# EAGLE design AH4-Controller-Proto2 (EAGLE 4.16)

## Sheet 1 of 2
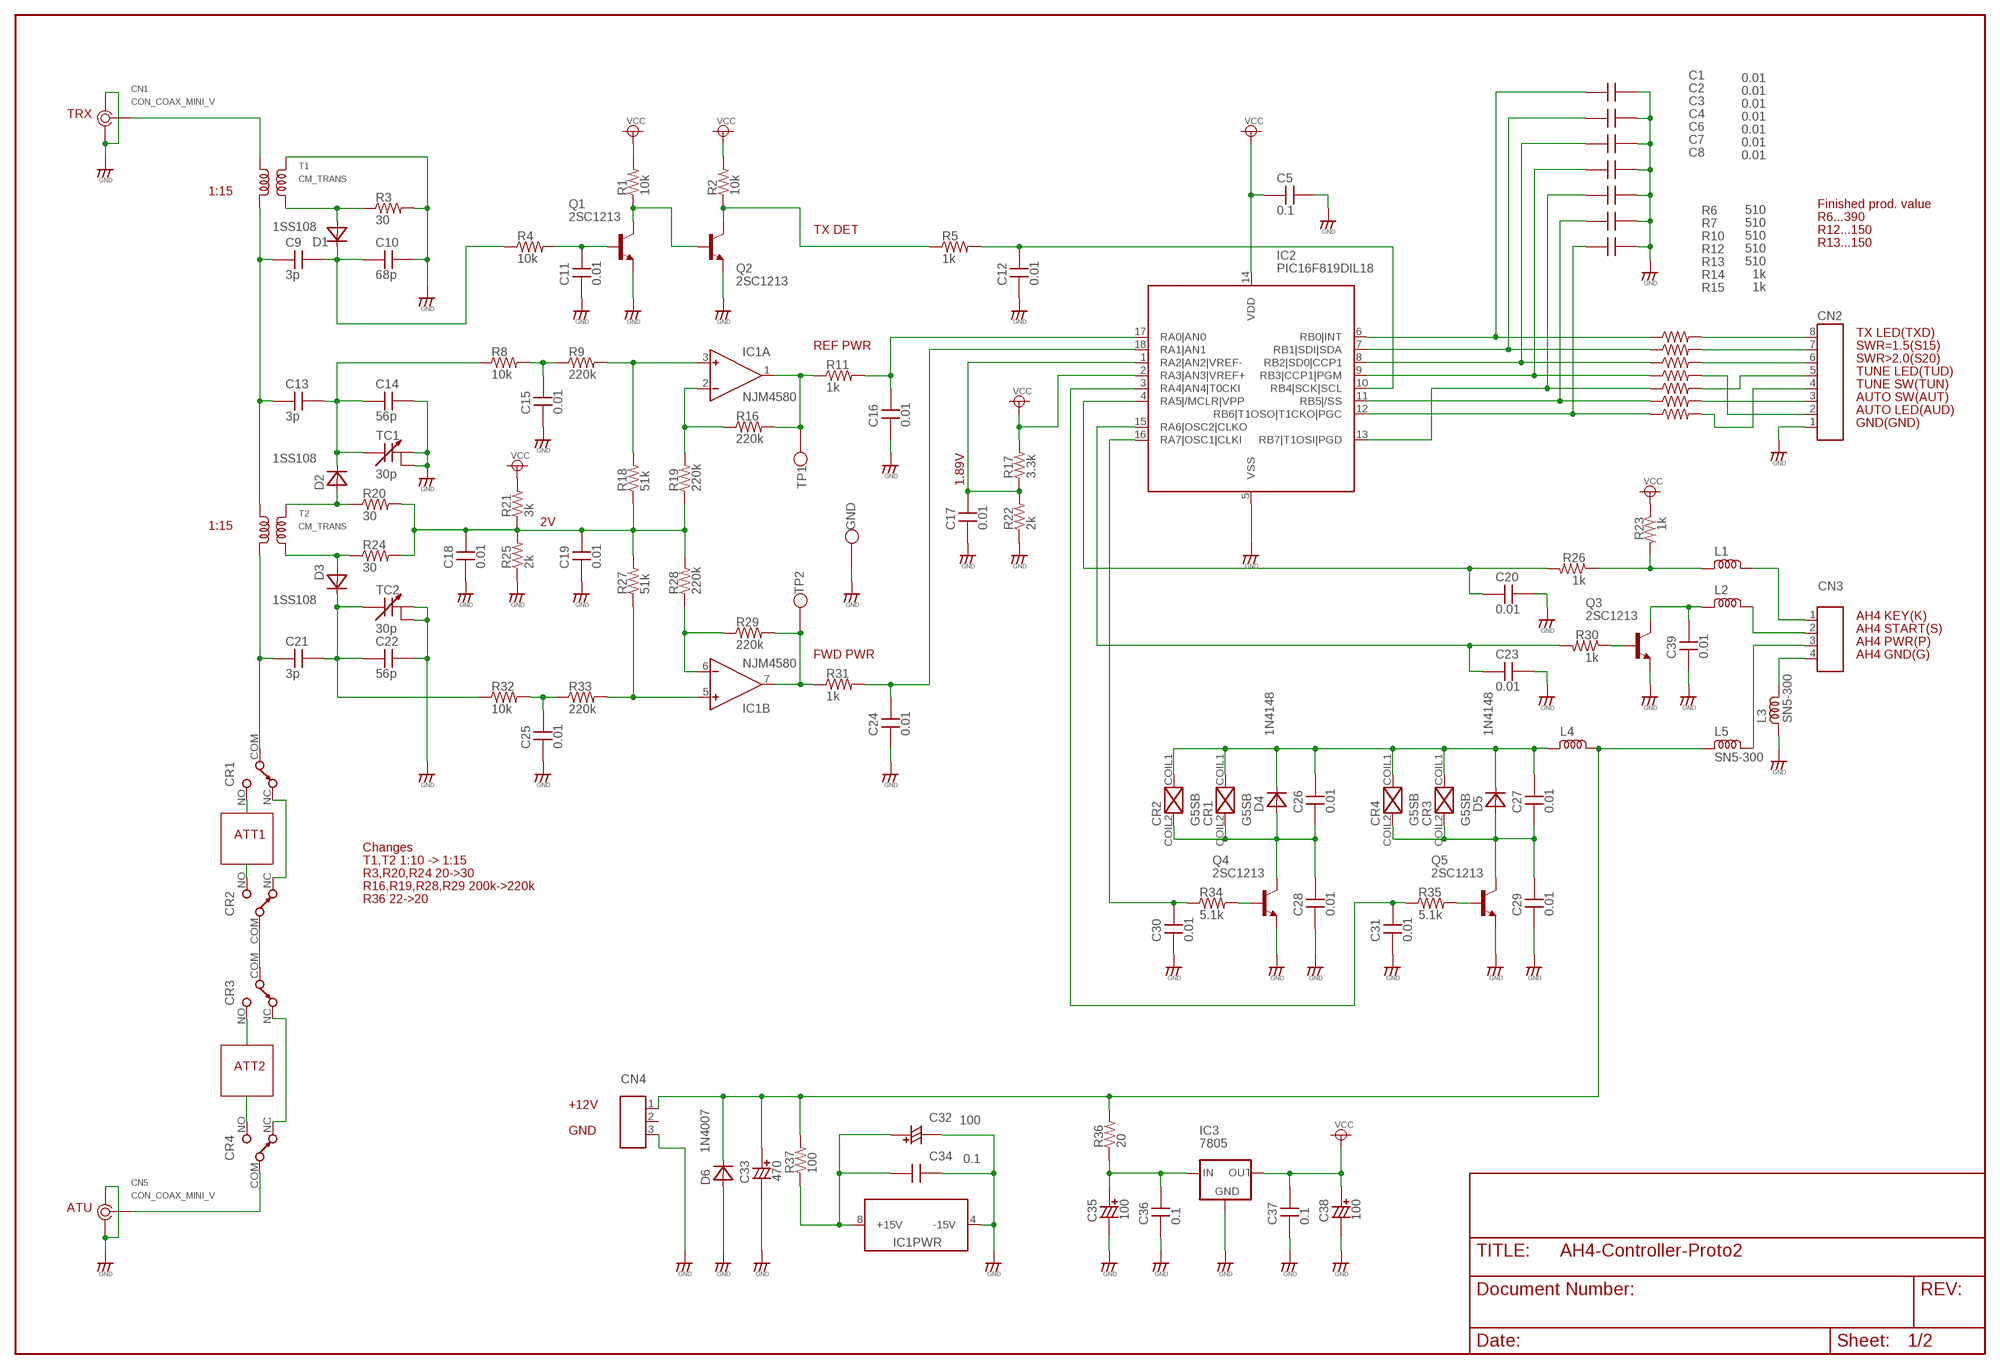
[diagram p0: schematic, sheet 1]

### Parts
C1  0.01  CAPDIP_2  [CAP_DIP_2]
C2  0.01  CAPDIP_2  [CAP_DIP_2]
C3  0.01  CAPDIP_2  [CAP_DIP_2]
C4  0.01  CAPDIP_2  [CAP_DIP_2]
C5  0.1  CAPDIP_2  [CAP_DIP_2]
C6  0.01  CAPDIP_2  [CAP_DIP_2]
C7  0.01  CAPDIP_2  [CAP_DIP_2]
C8  0.01  CAPDIP_2  [CAP_DIP_2]
C9  3p  CAPDIP_2  [CAP_DIP_2]
C10  68p  CAPDIP_2  [CAP_DIP_2]
C11  0.01  CAPDIP_2  [CAP_DIP_2]
C12  0.01  CAPDIP_2  [CAP_DIP_2]
C13  3p  CAPDIP_2  [CAP_DIP_2]
C14  56p  CAPDIP_2  [CAP_DIP_2]
C15  0.01  CAPDIP_2  [CAP_DIP_2]
C16  0.01  CAPDIP_2  [CAP_DIP_2]
C17  0.01  CAPDIP_2  [CAP_DIP_2]
C18  0.01  CAPDIP_2  [CAP_DIP_2]
C19  0.01  CAPDIP_2  [CAP_DIP_2]
C20  0.01  CAPDIP_2  [CAP_DIP_2]
C21  3p  CAPDIP_2  [CAP_DIP_2]
C22  56p  CAPDIP_2  [CAP_DIP_2]
C23  0.01  CAPDIP_2  [CAP_DIP_2]
C24  0.01  CAPDIP_2  [CAP_DIP_2]
C25  0.01  CAPDIP_2  [CAP_DIP_2]
C26  0.01  CAPDIP_2  [CAP_DIP_2]
C27  0.01  CAPDIP_2  [CAP_DIP_2]
C28  0.01  CAPDIP_2  [CAP_DIP_2]
C29  0.01  CAPDIP_2  [CAP_DIP_2]
C30  0.01  CAPDIP_2  [CAP_DIP_2]
C31  0.01  CAPDIP_2  [CAP_DIP_2]
C32  100  CCAP6.5  [CCAP_6.5]
C33  470  CCAP8.5  [CCAP_8.5]
C34  0.1  CAPDIP_2  [CAP_DIP_2]
C35  100  CCAP6.5  [CCAP_6.5]
C36  0.1  CAPDIP_2  [CAP_DIP_2]
C37  0.1  CAPDIP_2  [CAP_DIP_2]
C38  100  CCAP6.5  [CCAP_6.5]
C39  0.01  CAPDIP_2  [CAP_DIP_2]
CN1  CON_COAX_MINI_V  [CON_COAX_MINI_V]
CN2  CON_8P  [CON_HRS_DIP_8]
CN3  CON_4P  [CON_HRS_DIP_4]
CN4  CON_3P  [CON_HRS_DIP_3]
CN5  CON_COAX_MINI_V  [CON_COAX_MINI_V]
CR1  G5SB  [G5SB]
CR2  G5SB  [G5SB]
CR3  G5SB  [G5SB]
CR4  G5SB  [G5SB]
D1  1SS108  DIODEGENERIC_2  [DIODE_2]
D2  1SS108  DIODEGENERIC_2  [DIODE_2]
D3  1SS108  DIODEGENERIC_2  [DIODE_2]
D4  1N4148  DIODEGENERIC_2  [DIODE_2]
D5  1N4148  DIODEGENERIC_2  [DIODE_2]
D6  1N4007  DIODEGENERIC_3  [DIODE_3]
GND  TP  [TP]
IC1  NJM4580  [DIL08]
IC2  PIC16F819DIL18  [DIL18]
IC3  7805  78XXVIRT  [TO220-VIRT]
L1  L  [MICRO_INDUCTOR]
L2  L  [MICRO_INDUCTOR]
L3  SN5-300  LSN5-300  [SN5-300]
L4  L  [MICRO_INDUCTOR]
L5  SN5-300  LSN5-300  [SN5-300]
Q1  2SC1213  2SC1815  [TO92]
Q2  2SC1213  2SC1815  [TO92]
Q3  2SC1213  2SC1815  [TO92]
Q4  2SC1213  2SC2236  [TO92]
Q5  2SC1213  2SC2236  [TO92]
R1  10k  R0.125W_2P  [R_0.125W_2]
R2  10k  R0.125W_2P  [R_0.125W_2]
R3  30  R0.125W_2P  [R_0.125W_2]
R4  10k  R0.125W_2P  [R_0.125W_2]
R5  1k  R0.125W_2P  [R_0.125W_2]
R6  510  R0.125W_2P  [R_0.125W_2]
R7  510  R0.125W_2P  [R_0.125W_2]
R8  10k  R0.125W_2P  [R_0.125W_2]
R9  220k  R0.125W_2P  [R_0.125W_2]
R10  510  R0.125W_2P  [R_0.125W_2]
R11  1k  R0.125W_2P  [R_0.125W_2]
R12  510  R0.125W_2P  [R_0.125W_2]
R13  510  R0.125W_2P  [R_0.125W_2]
R14  1k  R0.125W_2P  [R_0.125W_2]
R15  1k  R0.125W_2P  [R_0.125W_2]
R16  220k  R0.125W_2P  [R_0.125W_2]
R17  3.3k  R0.125W_2P  [R_0.125W_2]
R18  51k  R0.125W_2P  [R_0.125W_2]
R19  220k  R0.125W_2P  [R_0.125W_2]
R20  30  R0.125W_2P  [R_0.125W_2]
R21  3k  R0.125W_2P  [R_0.125W_2]
R22  2k  R0.125W_2P  [R_0.125W_2]
R23  1k  R0.125W_2P  [R_0.125W_2]
R24  30  R0.125W_2P  [R_0.125W_2]
R25  2k  R0.125W_2P  [R_0.125W_2]
R26  1k  R0.125W_2P  [R_0.125W_2]
R27  51k  R0.125W_2P  [R_0.125W_2]
R28  220k  R0.125W_2P  [R_0.125W_2]
R29  220k  R0.125W_2P  [R_0.125W_2]
R30  1k  R0.125W_2P  [R_0.125W_2]
R31  1k  R0.125W_2P  [R_0.125W_2]
R32  10k  R0.125W_2P  [R_0.125W_2]
R33  220k  R0.125W_2P  [R_0.125W_2]
R34  5.1k  R0.125W_2P  [R_0.125W_2]
R35  5.1k  R0.125W_2P  [R_0.125W_2]
R36  20  R0.125W_2P  [R_0.125W_2]
R37  100  R0.125W_3P  [R_0.125W_3]
T1  CM_TRANS  [CM_TRANS]
T2  CM_TRANS  [CM_TRANS]
TC1  30p  TCAP  [TC_PHILLIPS]
TC2  30p  TCAP  [TC_PHILLIPS]
TP1  TP  [TP]
TP2  TP  [TP]

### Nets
12V: C33.+ CN4.1 D6.K L4.2 L5.1 R36.2 R37.2
ATT1_IN: CR1.NO ; also sheet 2
ATT1_OUT: CR2.NO ; also sheet 2
ATT2_IN: CR3.NO ; also sheet 2
ATT2_OUT: CR4.NO ; also sheet 2
CN1: CN1.HOT T1.P1
CN3: CN5.HOT CR4.COM
DVCC: C5.1 C37.2 C38.+ IC2.2(RA3|AN3|VREF+) IC2.14(VDD) IC3.3(OUT) R1.2 R2.2 R17.2 R21.2 R23.1 ; supply symbol labelled VCC
GND: C1.2 C2.2 C3.2 C4.2 C5.2 C6.2 C7.2 C8.2 C10.2 C11.1 C12.1 C14.2 C15.1 C16.1 C17.1 C18.1 C19.1 C20.2 C22.2 C23.2 C24.1 C25.1 C28.1 C29.1 C30.1 C31.1 C32.- C33.- C34.2 C35.- C36.1 C37.1 C38.- C39.1 CN1.COLD1 CN1.COLD2 CN2.1 CN4.3 CN5.COLD1 CN5.COLD2 D6.A GND.TP IC1.4(PWR:-15V) IC2.5(VSS) IC3.2(GND) L3.1 Q1.1(E) Q2.1(E) Q3.1(E) Q4.1(E) Q5.1(E) R3.2 R22.1 R25.1 T1.S1 TC1.ROT-1 TC1.ROT-2 TC2.ROT-1 TC2.ROT-2 ; also sheet 2
N$1: C15.2 R8.2 R9.1
N$2: IC1.3(A:IN+) R9.2 R18.2
N$3: IC1.2(A:IN-) R16.1 R19.2
N$4: C31.2 IC2.3(RA4|AN4|T0CKI) R35.1
N$5: C25.2 R32.2 R33.1
N$6: IC1.5(B:IN+) R27.1 R33.2
N$7: IC1.1(A:OUT) R11.1 R16.2 TP1.TP
N$8: C24.2 IC2.18(RA1|AN1) R31.2
N$9: C13.2 C14.1 D2.K R8.1 TC1.ST
N$10: C21.2 C22.1 D3.K R32.1 TC2.ST
N$11: C16.2 IC2.17(RA0|AN0) R11.2
N$12: L1.1 R23.2 R26.1
N$13: Q1.2(C) Q2.3(B) R1.1
N$14: C26.1 C28.2 CR1.COIL2 CR2.COIL2 D4.A Q4.2(C)
N$15: CN3.1 L1.2
N$16: C12.2 IC2.10(RB4|SCK|SCL) R5.2
N$17: C9.1 C13.1 T1.P2 T2.P1
N$18: C1.1 IC2.6(RB0|INT) R6.1
N$19: C2.1 IC2.7(RB1|SDI|SDA) R7.1
N$20: C7.1 IC2.11(RB5|/SS) R14.1
N$21: C4.1 IC2.9(RB3|CCP1|PGM) R12.1
N$22: CN3.2 L2.2
N$23: C8.1 IC2.12(RB6|T1OSO|T1CKO|PGC) R15.1
N$24: CN2.8 R6.2
N$25: CN2.7 R7.2
N$26: CN2.6 R10.2
N$27: CN2.2 R12.2
N$28: C6.1 IC2.13(RB7|T1OSI|PGD) R13.1
N$29: D1.A R3.1 T1.S2
N$30: IC1.6(B:IN-) R28.1 R29.1
N$31: IC1.7(B:OUT) R29.2 R31.1 TP2.TP
N$32: D3.A R24.1 T2.S2
N$33: CN3.3 L5.2
N$34: C18.2 C19.2 R18.1 R19.1 R20.2 R21.1 R24.2 R25.2 R27.2 R28.2
N$35: CN2.5 R13.2
N$36: Q3.3(B) R30.1
N$37: CN2.3 R14.2
N$38: C20.1 IC2.4(RA5|/MCLR|VPP) R26.2
N$39: C30.2 IC2.16(RA7|OSC1|CLKI) R34.1
N$41: C35.+ C36.2 IC3.1(IN) R36.1
N$42: C32.+ C34.1 IC1.8(PWR:+15V) R37.1
N$43: C23.1 IC2.15(RA6|OSC2|CLKO) R30.2
N$44: CN2.4 R15.2
N$45: C9.2 C10.1 D1.K R4.1
N$46: CN3.4 L3.2
N$47: C11.2 Q1.3(B) R4.2
N$48: C17.2 IC2.1(RA2|AN2|VREF-) R17.1 R22.2
N$49: Q2.2(C) R2.1 R5.1
N$50: CR1.NC CR2.NC
N$51: C39.2 L2.1 Q3.2(C)
N$52: C3.1 IC2.8(RB2|SD0|CCP1) R10.1
N$53: CR3.NC CR4.NC
N$54: C27.1 C29.2 CR3.COIL2 CR4.COIL2 D5.A Q5.2(C)
N$55: C21.1 CR1.COM T2.P2
N$56: CR2.COM CR3.COM
N$57: C26.2 C27.2 CR1.COIL1 CR2.COIL1 CR3.COIL1 CR4.COIL1 D4.K D5.K L4.1
N$58: Q5.3(B) R35.2
N$59: Q4.3(B) R34.2
T1: D2.A R20.1 T2.S1
Unconnected: CN4.2

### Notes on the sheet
- TRX
- 1:15
- Finished prod. value
- R6...390
- TX DET | R12...150
- R13...150
- TX LED(TXD)
- REF PWR | SWR=1.5(S15)
- SWR>2.0(S20)
- TUNE LED(TUD)
- TUNE SW(TUN)
- AUTO SW(AUT)
- AUTO LED(AUD)
- GND(GND)
- 1.89V
- 2V
- 1:15
- AH4 KEY(K)
- AH4 START(S)
- AH4 PWR(P)
- FWD PWR | AH4 GND(G)
- ATT1
- Changes
- T1,T2 1:10 -> 1:15
- R3,R20,R24 20->30
- R16,R19,R28,R29 200k->220k
- R36 22->20
- ATT2
- +12V
- GND
- ATU

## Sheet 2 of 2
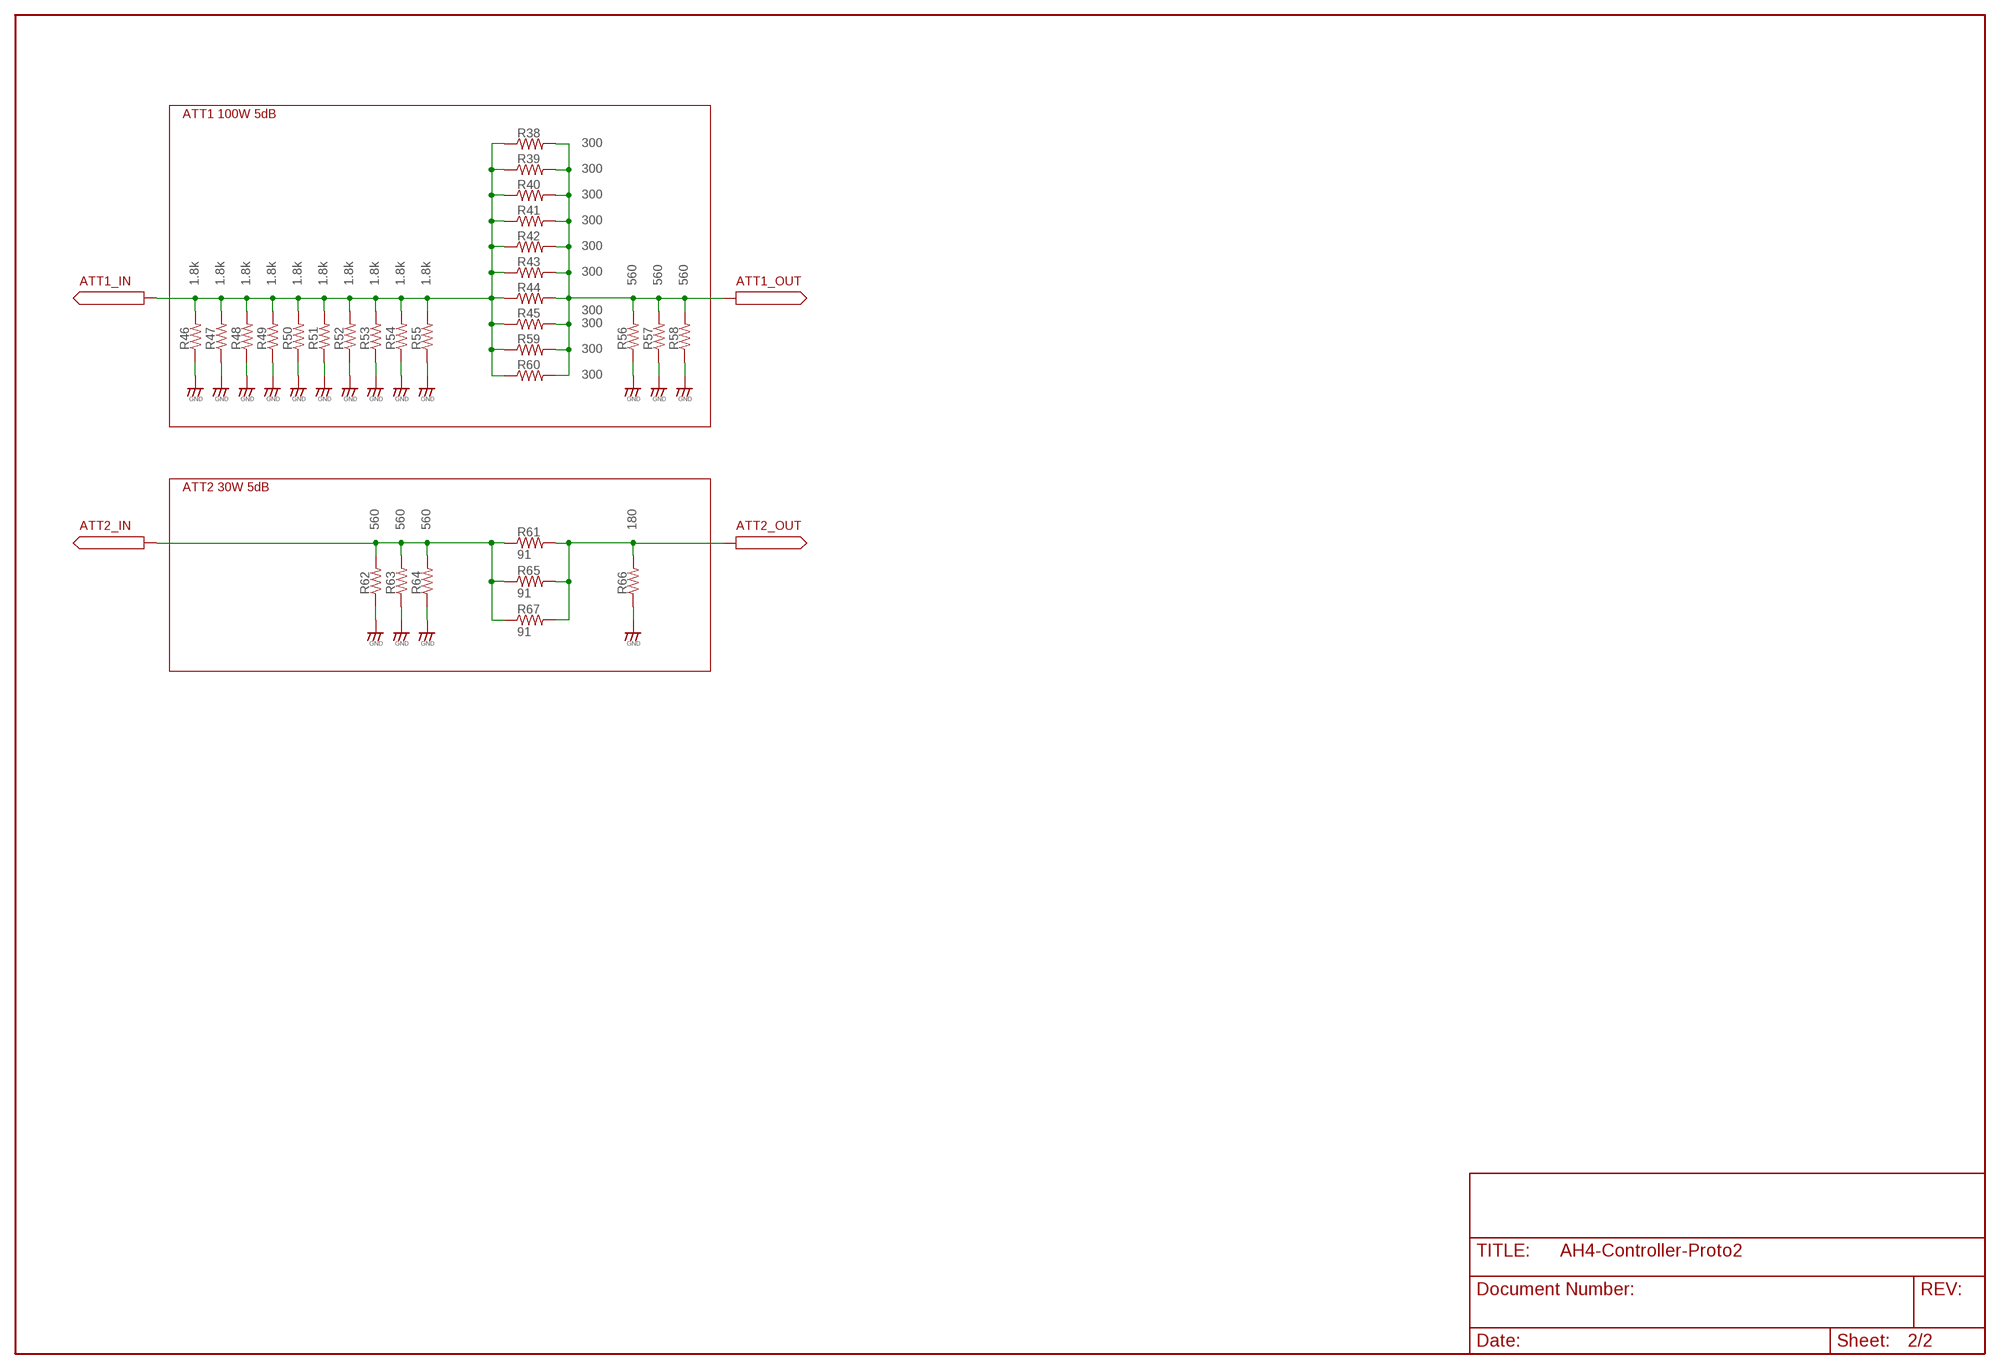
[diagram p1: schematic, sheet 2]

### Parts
R38  300  R3W_7  [R_3W_7]
R39  300  R3W_7  [R_3W_7]
R40  300  R3W_7  [R_3W_7]
R41  300  R3W_7  [R_3W_7]
R42  300  R3W_7  [R_3W_7]
R43  300  R3W_7_STACK  [R_3W_7_STACK]
R44  300  R3W_7_STACK  [R_3W_7_STACK]
R45  300  R3W_7_STACK  [R_3W_7_STACK]
R46  1.8k  R3W_7  [R_3W_7]
R47  1.8k  R3W_7  [R_3W_7]
R48  1.8k  R3W_7  [R_3W_7]
R49  1.8k  R3W_7  [R_3W_7]
R50  1.8k  R3W_7  [R_3W_7]
R51  1.8k  R3W_7_STACK  [R_3W_7_STACK]
R52  1.8k  R3W_7_STACK  [R_3W_7_STACK]
R53  1.8k  R3W_7_STACK  [R_3W_7_STACK]
R54  1.8k  R3W_7_STACK  [R_3W_7_STACK]
R55  1.8k  R3W_7_STACK  [R_3W_7_STACK]
R56  560  R3W_7  [R_3W_7]
R57  560  R3W_7  [R_3W_7]
R58  560  R3W_7_STACK  [R_3W_7_STACK]
R59  300  R3W_7_STACK  [R_3W_7_STACK]
R60  300  R3W_7_STACK  [R_3W_7_STACK]
R61  91  R3W_7  [R_3W_7]
R62  560  R3W_7_STACK  [R_3W_7_STACK]
R63  560  R3W_7  [R_3W_7]
R64  560  R3W_7  [R_3W_7]
R65  91  R3W_7_STACK  [R_3W_7_STACK]
R66  180  R3W_7  [R_3W_7]
R67  91  R3W_7  [R_3W_7]

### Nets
ATT1_IN: R38.1 R39.1 R40.1 R41.1 R42.1 R43.1 R44.1 R45.1 R46.2 R47.2 R48.2 R49.2 R50.2 R51.2 R52.2 R53.2 R54.2 R55.2 R59.1 R60.1 ; also sheet 1
ATT1_OUT: R38.2 R39.2 R40.2 R41.2 R42.2 R43.2 R44.2 R45.2 R56.2 R57.2 R58.2 R59.2 R60.2 ; also sheet 1
ATT2_IN: R61.1 R62.2 R63.2 R64.2 R65.1 R67.1 ; also sheet 1
ATT2_OUT: R61.2 R65.2 R66.2 R67.2 ; also sheet 1
GND: R46.1 R47.1 R48.1 R49.1 R50.1 R51.1 R52.1 R53.1 R54.1 R55.1 R56.1 R57.1 R58.1 R62.1 R63.1 R64.1 R66.1 ; also sheet 1

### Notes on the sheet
- ATT1 100W 5dB
- ATT1_IN | ATT1_OUT
- ATT2 30W 5dB
- ATT2_IN | ATT2_OUT

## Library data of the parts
C1-C31 C34 C36 C37 C39 = AH4-Controller:CAP: Non polar capacitor
C32 C33 C35 C38 = AH4-Controller:CCAP: Polar capacitor
CN1 CN5 = AH4-Controller:CON_COAX_MINI_V
CN2 = AH4-Controller:CON_8P
CN3 = AH4-Controller:CON_4P
CN4 = AH4-Controller:CON_3P
CR1-CR4 = AH4-Controller:G5SB
D1-D6 = AH4-Controller:DIODE
GND TP1 TP2 = AH4-Controller:TP
IC1 = AH4-Controller:NJM4580: Audio opamp
IC2 = AH4-Controller:PIC16F819: PIC MICRO (16 I/O 10bit-5ch ADC 20MHz)
IC3 = AH4-Controller:78XX
L1-L5 = AH4-Controller:L
Q1-Q3 = AH4-Controller:2SC1815: General use NPN transistor
Q4 Q5 = AH4-Controller:2SC2236
R1-R67 = AH4-Controller:R
T1 T2 = AH4-Controller:CM_TRANS
TC1 TC2 = AH4-Controller:TCAP

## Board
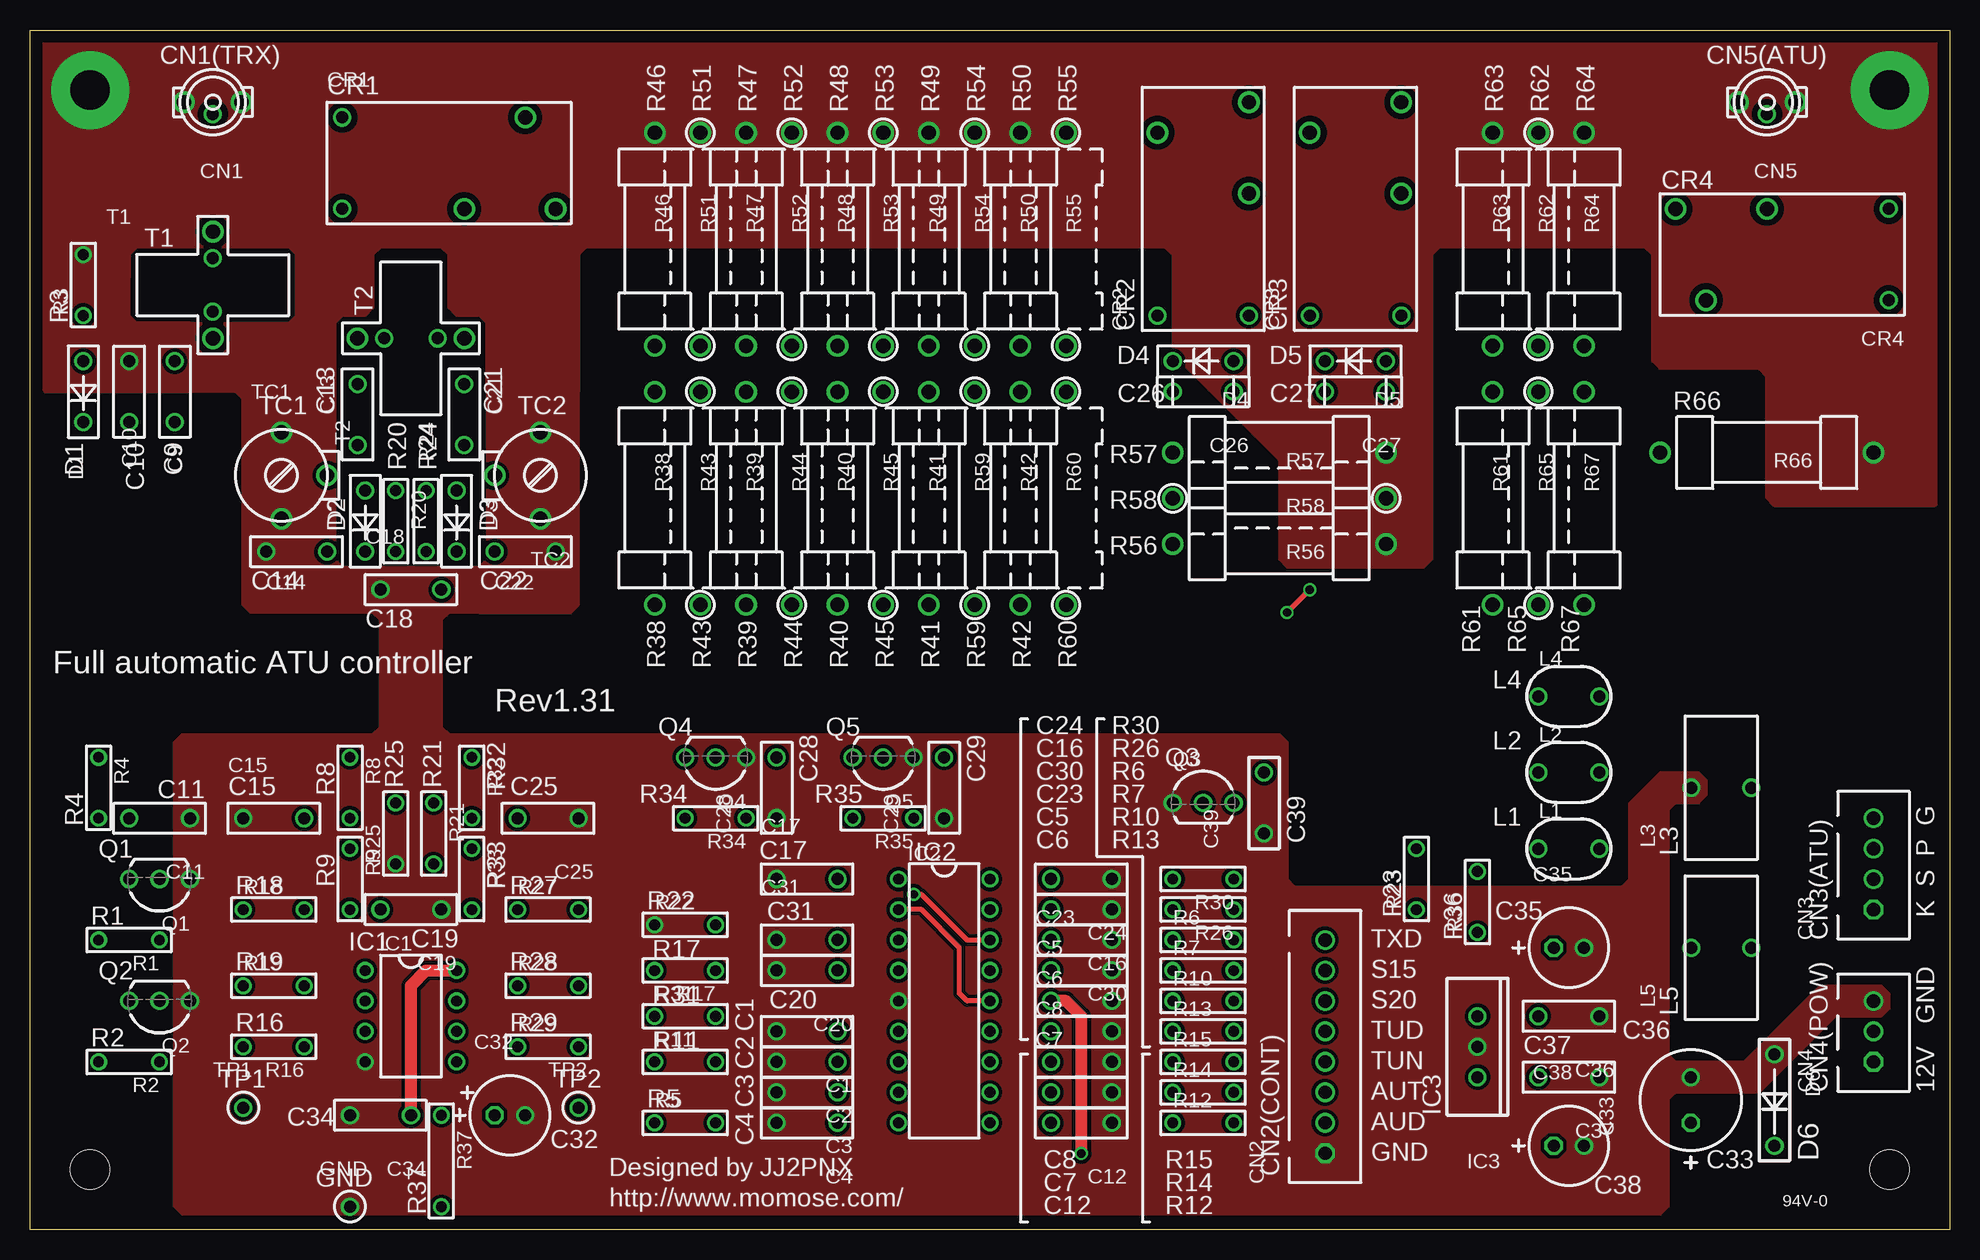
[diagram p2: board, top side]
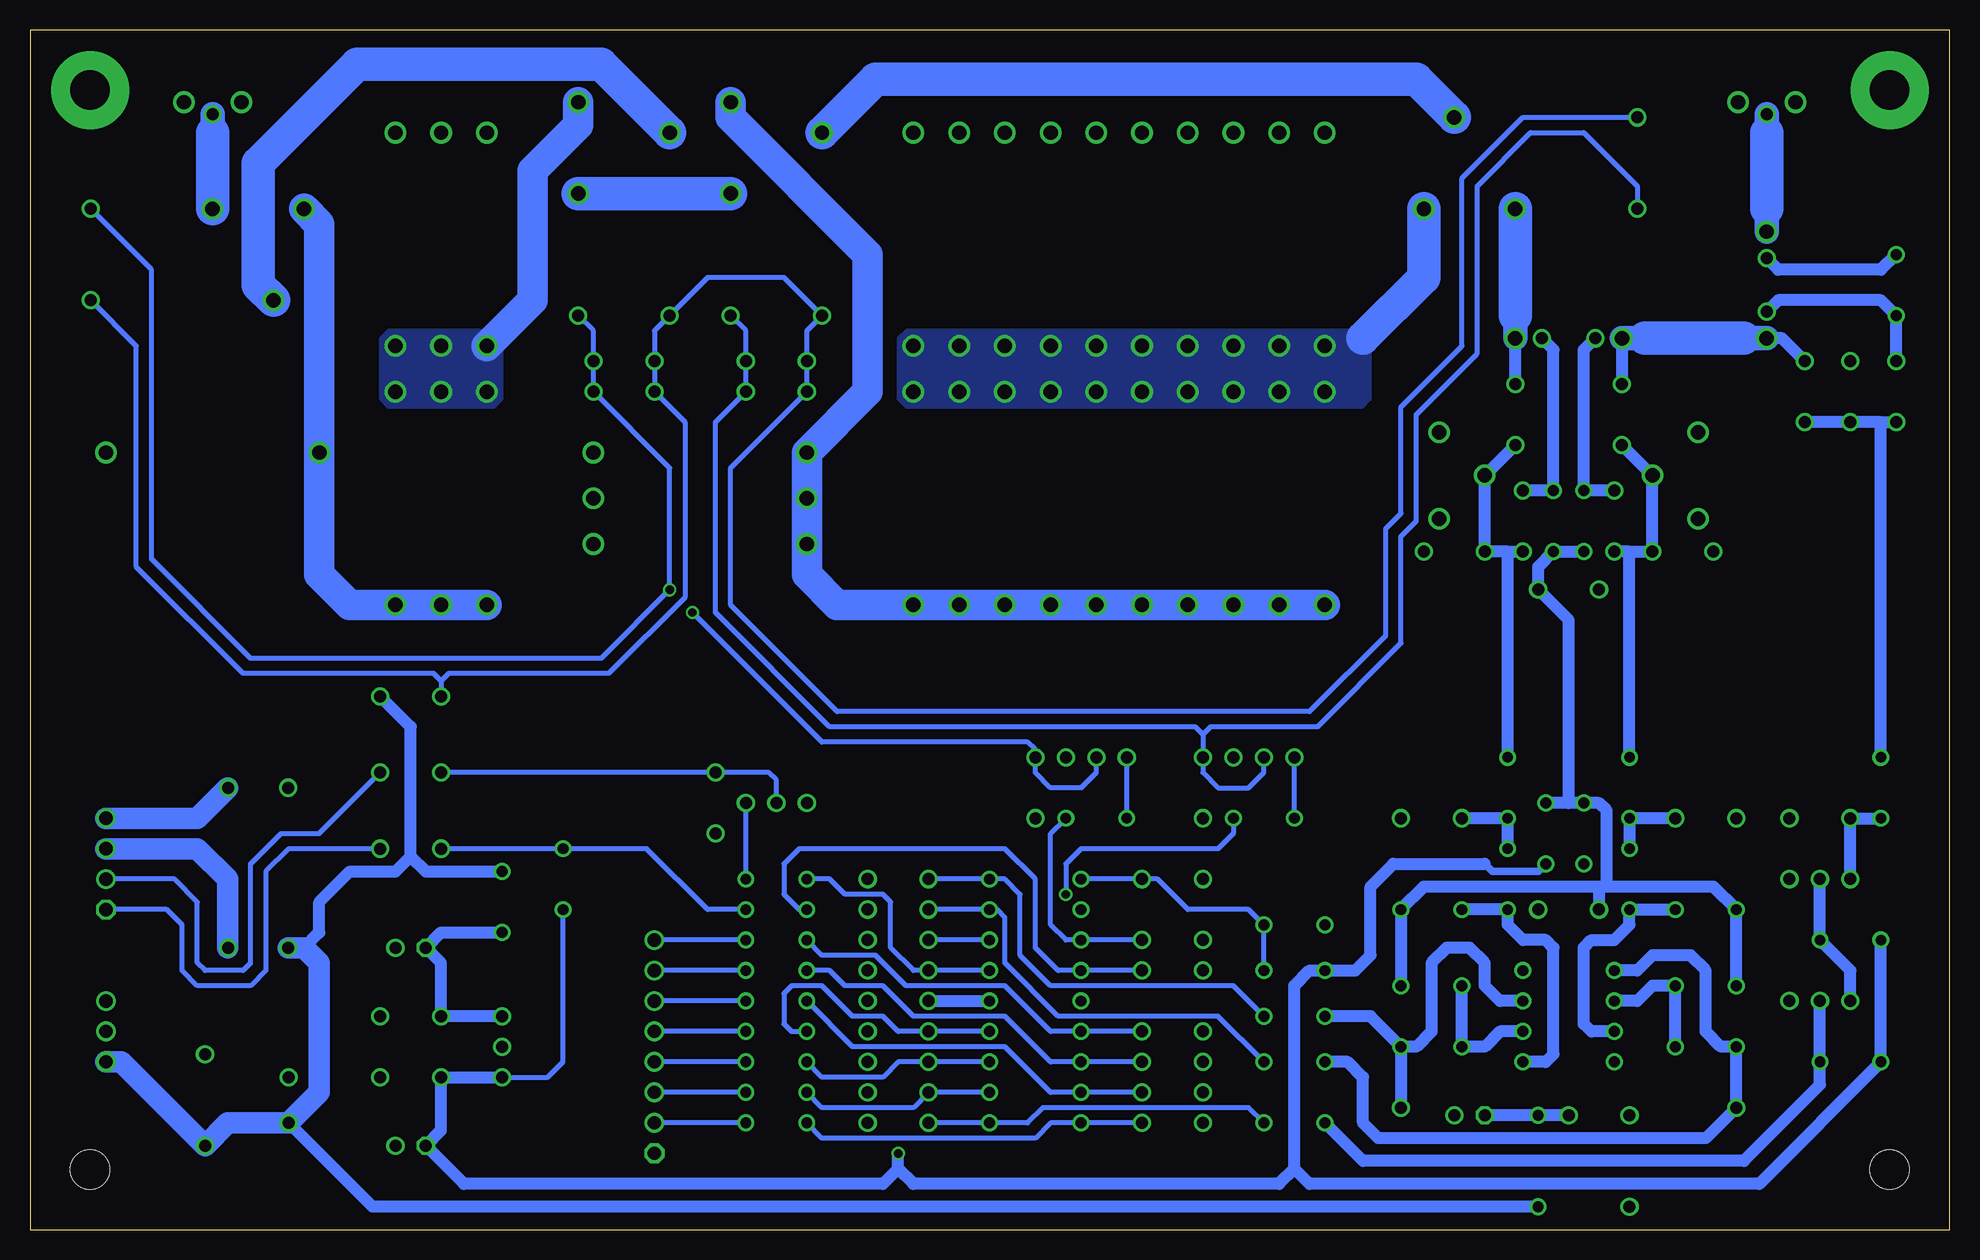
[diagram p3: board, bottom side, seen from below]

Size 160 x 100 mm. Coordinates in mm from the lower left corner, seen from the top.
Outline: 0,0 0,100 160,100 160,0 0,0
Copper layers (1*16): Top 0.035mm / dielectric 1.5mm / Bottom 0.035mm
Design rules "Olimex10mils": minimum track width 10mil, minimum drill 24mil, track to track 10mil, track to pad 10mil, pad to pad 10mil, via to via 10mil, smd to smd 10mil, copper to edge 40mil, drill to drill 10mil, minimum pad ring 10mil, minimum via ring 8mil, stop-mask expansion 0mil, vias tented up to drill 0mil, thermal gap 10mil
Holes 3.3 mm at 5,5 155,5

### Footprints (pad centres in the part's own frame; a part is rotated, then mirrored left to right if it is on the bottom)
CAP_DIP_2 = drill 1 round: 1 -2.54,0; 2 2.54,0
CCAP_6.5 = drill 1 octagon: + -1.27,0 | drill 1 round: - 1.27,0
CCAP_8.5 = drill 1 octagon: + -1.905,0 | drill 1 round: - 1.905,0
CON_COAX_MINI_V = drill 1.2 round: COLD1 -2.4,0; COLD2 2.4,0 | drill 1 round: HOT 0,1
CON_HRS_DIP_8 = drill 1.1 octagon: 1 -8.89,0 | drill 1.1 round: 2 -6.35,0; 3 -3.81,0; 4 -1.27,0; 5 1.27,0; 6 3.81,0; 7 6.35,0; 8 8.89,0
CON_HRS_DIP_4 = drill 1.1 octagon: 1 -3.81,0 | drill 1.1 round: 2 -1.27,0; 3 1.27,0; 4 3.81,0
CON_HRS_DIP_3 = drill 1.1 octagon: 1 -2.54,0 | drill 1.1 round: 2 0,0; 3 2.54,0
G5SB = drill 1 round: COIL1 -8.89,3.81; COIL2 -8.89,-3.81 | drill 1.2 round: COM 1.27,-3.81; NC 6.35,3.81; NO 8.89,-3.81
DIODE_2 = drill 1 round: A -2.54,0; K 2.54,0
DIODE_3 = drill 1 round: A -3.81,0; K 3.81,0
TP = drill 1 round: TP 0,0
DIL08 = drill 0.9 round: 1 -3.81,-3.81; 2 -1.27,-3.81; 3 1.27,-3.81; 4 3.81,-3.81; 5 3.81,3.81; 6 1.27,3.81; 7 -1.27,3.81; 8 -3.81,3.81
DIL18 = drill 0.9 round: 1 -10.16,-3.81; 2 -7.62,-3.81; 3 -5.08,-3.81; 4 -2.54,-3.81; 5 0,-3.81; 6 2.54,-3.81; 7 5.08,-3.81; 8 7.62,-3.81; 9 10.16,-3.81; 10 10.16,3.81; 11 7.62,3.81; 12 5.08,3.81; 13 2.54,3.81; 14 0,3.81; 15 -2.54,3.81; 16 -5.08,3.81; 17 -7.62,3.81; 18 -10.16,3.81
TO220-VIRT = drill 1 round: 1 0,-2.54; 2 0,0; 3 0,2.54
MICRO_INDUCTOR = drill 1 round: 1 -2.54,0; 2 2.54,0
SN5-300 = drill 1 round: 1 0,2.5; 2 0,-2.5
TO92 = drill 1 round: 1 -2.54,0; 2 0,0; 3 2.54,0
R_0.125W_2 = drill 0.9 round: 1 -2.54,0; 2 2.54,0
R_0.125W_3 = drill 0.9 round: 1 -3.81,0; 2 3.81,0
R_3W_7 = drill 1.2 round: 1 -8.89,0; 2 8.89,0
R_3W_7_STACK = drill 1.2 round: 1 -8.89,0; 2 8.89,0
CM_TRANS = drill 1.2 round: P1 0,4.445; P2 0,-4.445 | drill 1 round: S1 0,2.223; S2 0,-2.223
TC_PHILLIPS = drill 1.2 round: ROT-1 0,3.6; ROT-2 0,-3.6; ST 3.8,0

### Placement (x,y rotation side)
C1  64.77,16.51 180 top
C2  64.77,13.97 180 top
C3  64.77,11.43 180 top
C4  64.77,8.89 180 top
C5  87.63,19.05 0 top
C6  87.63,16.51 0 top
C7  87.63,11.43 0 top
C8  87.63,13.97 0 top
C9  12.06,69.85 270 top
C10  8.26,69.85 90 top
C11  10.79,34.29 180 top
C12  87.63,8.89 180 top
C13  27.3,67.94 270 top
C14  22.23,56.52 180 top
C15  20.32,34.29 0 top
C16  87.63,26.67 180 top
C17  64.77,29.21 0 top
C18  31.75,53.34 0 top
C19  31.75,26.67 180 top
C20  64.77,21.59 180 top
C21  36.2,67.94 270 top
C22  41.27,56.52 0 top
C23  87.63,21.59 0 top
C24  87.63,29.21 180 top
C25  43.18,34.29 180 top
C26  97.79,69.85 180 top
C27  110.49,69.85 180 top
C28  62.23,36.83 90 top
C29  76.2,36.83 90 top
C30  87.63,24.13 180 top
C31  64.77,24.13 0 top
C32  40.01,9.53 0 top
C33  138.43,10.79 90 top
C34  29.21,9.53 180 top
C35  128.27,23.5 0 top
C36  128.27,17.78 180 top
C37  128.27,12.7 180 top
C38  128.27,6.99 0 top
C39  102.87,35.56 90 top
CN1  15.24,93.98 180 top
CN2  107.95,15.24 90 top
CN3  153.67,30.48 90 top
CN4  153.67,16.51 90 top
CN5  144.78,93.98 180 top
CR1  34.92,88.9 0 top
CR2  97.79,85.09 90 top
CR3  110.49,85.09 90 top
CR4  146.05,81.28 180 top
D1  4.45,69.85 270 top
D2  27.94,59.05 270 top
D3  35.56,59.05 270 top
D4  97.79,72.39 180 top
D5  110.49,72.39 180 top
D6  145.41,10.79 270 top
GND  26.67,1.91 0 top
IC1  31.75,17.78 270 top
IC2  76.2,19.05 270 top
IC3  120.65,15.24 180 top
L1  128.27,31.75 0 top
L2  128.27,38.1 0 top
L3  140.97,36.83 90 top
L4  128.27,44.45 0 top
L5  140.97,23.5 90 top
Q1  10.79,29.21 180 top
Q2  10.79,19.05 180 top
Q3  97.79,35.56 0 top
Q4  57.15,39.37 180 top
Q5  71.12,39.37 180 top
R1  8.26,24.13 180 top
R2  8.26,13.97 180 top
R3  4.45,78.74 90 top
R4  5.71,36.83 270 top
R5  54.61,8.89 0 top
R6  97.79,24.13 0 top
R7  97.79,21.59 0 top
R8  26.67,36.83 270 top
R9  26.67,29.21 270 top
R10  97.79,19.05 0 top
R11  54.61,13.97 0 top
R12  97.79,8.89 0 top
R13  97.79,16.51 0 top
R14  97.79,11.43 0 top
R15  97.79,13.97 0 top
R16  20.32,15.24 180 top
R17  54.61,21.59 180 top
R18  20.32,26.67 0 top
R19  20.32,20.32 0 top
R20  30.48,59.05 270 top
R21  33.66,33.02 270 top
R22  54.61,25.4 0 top
R23  115.57,29.21 90 top
R24  33.02,59.05 270 top
R25  30.48,33.02 90 top
R26  97.79,26.67 180 top
R27  43.18,26.67 0 top
R28  43.18,20.32 0 top
R29  43.18,15.24 0 top
R30  97.79,29.21 180 top
R31  54.61,17.78 0 top
R32  36.83,36.83 270 top
R33  36.83,29.21 270 top
R34  57.15,34.29 180 top
R35  71.12,34.29 180 top
R36  120.65,27.3 90 top
R37  34.29,5.71 270 top
R38  52.07,60.96 270 top
R39  59.69,60.96 270 top
R40  67.31,60.96 270 top
R41  74.93,60.96 270 top
R42  82.55,60.96 270 top
R43  55.88,60.96 270 top
R44  63.5,60.96 270 top
R45  71.12,60.96 270 top
R46  52.07,82.55 270 top
R47  59.69,82.55 270 top
R48  67.31,82.55 270 top
R49  74.93,82.55 270 top
R50  82.55,82.55 270 top
R51  55.88,82.55 270 top
R52  63.5,82.55 270 top
R53  71.12,82.55 270 top
R54  78.74,82.55 270 top
R55  86.36,82.55 270 top
R56  104.14,57.15 180 top
R57  104.14,64.77 180 top
R58  104.14,60.96 180 top
R59  78.74,60.96 270 top
R60  86.36,60.96 270 top
R61  121.92,60.96 270 top
R62  125.73,82.55 270 top
R63  121.92,82.55 270 top
R64  129.54,82.55 270 top
R65  125.73,60.96 270 top
R66  144.78,64.77 180 top
R67  129.54,60.96 270 top
T1  15.24,78.74 0 top
T2  31.75,74.3 90 top
TC1  20.95,62.87 0 top
TC2  42.55,62.87 180 top
TP1  17.78,10.16 0 top
TP2  45.72,10.16 0 top

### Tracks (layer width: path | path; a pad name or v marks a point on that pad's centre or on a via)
12V
  Bottom 1.016: 128.27,31.11 129.54,29.84 133.35,29.84 135.89,27.3 135.89,24.77 137.16,23.5 | L4.2 128.27,41.91 128.27,31.11 | 128.27,31.11 127,29.84 R36.2 | R37.2 131.44,1.91 C33.+
  Bottom 1.778: L5.1 137.16,23.5 135.89,22.23 135.89,11.43 C33.+ 143.51,8.89 D6.K 152.4,13.97 CN4.1
ATT1_IN
  Bottom 2.794: CR1.NO 43.81,79.38 48.9,74.3
  pour Bottom (no thermals): 48.26,74.93 87,74.93 87.63,74.3 87.63,69.22 87,68.58 48.9,68.58 48.26,69.22
ATT1_OUT
  Bottom 2.54: R38.2 R43.2 R39.2 R44.2 R40.2 R45.2 R41.2 R59.2 R42.2 R60.2 92.71,52.07 95.25,54.61 R56.2 R58.2 R57.2 90.17,69.85 90.17,81.28 101.6,92.71 CR2.NO
ATT2_IN
  Bottom 2.54: R63.2 118.11,77.47 118.11,88.27 114.3,92.08 CR3.NO
  pour Bottom (no thermals): 120.65,74.93 130.18,74.93 130.81,74.3 130.81,69.22 130.18,68.58 121.28,68.58 120.65,69.22
ATT2_OUT
  Bottom 2.54: R61.2 R65.2 R67.2 133.35,52.07 135.89,54.61 R66.2 135.89,83.82 CR4.NO
CN1
  Bottom 2.032: T1.P1 15.24,85.09 | 15.24,91.44 CN1.HOT
  Bottom 2.794: 15.24,85.09 15.24,91.44
CN3
  Bottom 2.032: 144.78,91.44 CN5.HOT
  Bottom 2.794: CR4.COM 144.78,91.44
DVCC  (via drill 0.7)
  Top 0.406: IC2.14 78.11,19.05 77.47,19.68 77.47,23.5 74.3,26.67 IC2.2
  Top 1.016: v87.63,6.35 87.63,17.78 86.36,19.05 C5.1
  Bottom 0.406: R23.1 115.57,13.97 116.84,12.7 IC3.3
  Bottom 0.61: R21.2 34.29,29.84 38.1,29.84 38.73,30.48
  Bottom 1.016: R1.2 R2.2 15.88,3.81 53.34,3.81 54.61,5.08 | C5.1 IC2.14 | 38.73,30.48 46.35,30.48 48.26,28.57 48.26,22.86 49.53,21.59 R17.2 53.34,21.59 54.61,20.32 54.61,5.08 | IC3.3 C37.2 125.73,8.26 C38.+ 123.83,3.81 88.9,3.81 87.63,5.08 | 54.61,5.08 55.88,3.81 86.36,3.81 87.63,5.08 | 87.63,5.08 v87.63,6.35
GND  (via drill 3.3 pad 6.5)
  Bottom 1.016: T1.S1 14.29,80.01 5.71,80.01 R3.2
  other vias: 5,95 155,95
  pour Top (isolate 0.508, no thermals): 0.64,98.42 1.27,99.06 158.75,99.06 159.38,98.42 159.38,60.96 158.75,60.33 145.41,60.33 144.78,60.96 144.78,71.12 144.15,71.75 135.89,71.75 135.25,72.39 135.25,81.28 134.62,81.92 46.35,81.92 45.72,81.28 45.72,69.85 38.1,69.85 38.1,75.56 37.47,76.2 35.56,76.2 34.92,76.83 34.92,81.28 34.29,81.92 29.21,81.92 28.57,81.28 28.57,76.83 27.94,76.2 26.04,76.2 25.4,75.56 25.4,69.85 13.34,69.85 13.34,75.56 21.59,75.56 22.23,76.2 22.23,81.28 21.59,81.92 8.89,81.92 8.26,81.28 8.26,79.38 0.64,79.38
  pour Top (isolate 0.305, no thermals): 12.06,1.91 12.06,40.64 12.7,41.27 104.14,41.27 104.78,40.64 104.78,29.21 105.41,28.57 132.72,28.57 133.35,29.21 133.35,35.56 135.89,38.1 139.06,38.1 139.7,37.47 139.7,36.2 139.06,35.56 137.16,35.56 136.53,34.92 136.53,14.61 137.16,13.97 142.88,13.97 149.22,20.32 154.31,20.32 154.94,19.68 154.94,18.41 154.31,17.78 150.5,17.78 144.15,11.43 137.16,11.43 136.53,10.79 136.53,1.91 135.89,1.27 12.7,1.27
  pour Top (isolate 0.305, no thermals): 26.04,55.24 37.47,55.24 37.47,51.44 34.92,51.44 34.29,50.8 34.29,41.91 34.92,41.27 28.57,41.27 29.21,41.91 29.21,50.8 28.57,51.44 26.04,51.44
  pour Top (isolate 0.305, no thermals): 94.61,81.92 95.25,81.28 95.25,73.03 104.14,64.14 104.14,55.88 104.78,55.24 116.2,55.24 116.84,55.88 116.84,81.28 117.47,81.92
  pour Top (isolate 0.305, no thermals): 38.1,69.85 38.1,55.88 37.47,55.24 37.47,51.44 45.09,51.44 45.72,52.07 45.72,69.85
  pour Top (isolate 0.305, no thermals): 25.4,69.85 25.4,55.88 26.04,55.24 26.04,51.44 18.41,51.44 17.78,52.07 17.78,69.22 17.14,69.85
  pour Top (isolate 0.305, no thermals): 13.34,75.56 8.89,75.56 8.26,76.2 8.26,79.38 0.64,79.38 0.64,70.48 1.27,69.85 13.34,69.85
N$1
  Bottom 1.016: C15.2 R8.2 R9.1
N$2
  Bottom 1.016: R18.2 R9.2 26.67,25.4 27.94,24.13 29.84,24.13 30.48,23.5 30.48,17.14 29.84,16.51 IC1.3
N$3
  Bottom 1.016: R16.1 R19.2 24.77,20.32 26.04,19.05 IC1.2
N$4
  Bottom 0.406: C31.2 IC2.3 73.66,24.13 74.93,25.4 74.93,33.02 R35.1
N$5
  Bottom 1.016: C25.2 R32.2 R33.1
N$6
  Bottom 1.016: R27.1 R33.2 36.83,25.4 35.56,24.13 33.66,24.13 33.02,23.5 33.02,14.61 33.66,13.97 IC1.5
N$7
  Bottom 1.016: IC1.1 26.04,21.59 24.77,22.86 21.59,22.86 20.32,21.59 20.32,16.51 19.05,15.24 R16.2 TP1.TP 20.32,7.62 47.62,7.62 48.9,8.89 48.9,12.7 50.16,13.97 R11.1
N$8
  Bottom 0.406: C24.2 IC2.18 78.74,29.21 77.47,27.94 77.47,22.86 74.93,20.32 59.69,20.32 R31.2
N$9
  Bottom 1.016: 24.77,62.87 C13.2 | 24.77,62.87 TC1.ST | 24.77,62.87 C14.1 26.67,56.52 | 26.67,56.52 D2.K | R8.1 26.67,56.52
N$10
  Bottom 1.016: 36.83,56.52 C22.1 38.73,62.87 | 38.73,62.87 TC2.ST | 38.73,62.87 C21.2 | 36.83,56.52 D3.K | R32.1 36.83,56.52
N$11
  Bottom 0.406: C16.2 IC2.17 79.38,26.67 78.74,26.04 78.74,22.23 74.3,17.78 60.96,17.78 R11.2
N$12
  Bottom 0.406: L1.1 R23.2 108.58,31.75 103.5,26.67 R26.1
N$13
  Bottom 1.016: Q1.2 R1.1 8.26,21.59 Q2.3
N$14
  Bottom 0.406: CR2.COIL2 100.33,74.93 D4.A C26.1 102.87,67.31 102.87,51.44 93.34,41.91 62.87,41.91 62.23,41.27 | 62.23,41.27 61.59,41.91 52.7,41.91 45.72,48.9 45.72,57.78 44.45,59.05 44.45,67.94 39.37,73.03 39.37,87 34.92,91.44 30.48,91.44 26.04,87 CR1.COIL2 | Q4.2 57.15,38.1 58.42,36.83 60.96,36.83 62.23,38.1 C28.2 62.23,41.27
N$15
  Bottom 0.406: L1.2 138.43,31.75 140.34,29.84 140.34,21.59 141.6,20.32 146.05,20.32 147.32,21.59 147.32,25.4 148.59,26.67 CN3.1
N$16
  Bottom 0.406: C12.2 IC2.10 76.83,8.89 75.56,10.16 58.42,10.16 R5.2
N$17
  Bottom 1.016: T2.P1 C13.1 | T1.P2 13.97,74.3 C9.1
  Bottom 2.032: T1.P2 17.14,74.3 | 25.4,74.3 T2.P1
  Bottom 2.794: 17.14,74.3 25.4,74.3
N$18
  Bottom 0.406: R6.1 93.98,22.86 89.53,22.86 87,20.32 78.74,20.32 74.93,16.51 IC2.6 C1.1
N$19
  Bottom 0.406: R7.1 93.34,21.59 92.08,20.32 88.9,20.32 86.36,17.78 78.74,17.78 74.93,13.97 IC2.7 C2.1
N$20
  Bottom 0.406: IC2.11 C7.1 86.36,10.16 93.98,10.16 R14.1
N$21
  Bottom 0.406: R12.1 93.98,7.62 76.2,7.62 74.93,8.89 IC2.9 C4.1
N$22
  Bottom 0.406: L2.2 135.89,33.02 139.06,33.02 141.6,30.48 141.6,22.23 142.24,21.59 145.41,21.59 146.05,22.23 146.05,27.3 147.96,29.21 CN3.2
N$23
  Bottom 0.406: IC2.12 C8.1 87.63,13.97 88.9,12.7 93.98,12.7 R15.1
N$24
  Bottom 0.406: R6.2 CN2.8
N$25
  Bottom 0.406: R7.2 CN2.7
N$26
  Bottom 0.406: R10.2 CN2.6
N$27
  Bottom 0.406: R12.2 CN2.2
N$28
  Bottom 0.406: IC2.13 C6.1 87.63,16.51 88.9,17.78 91.44,17.78 93.98,20.32 96.52,20.32 97.16,19.68 97.16,17.14 96.52,16.51 R13.1
N$29
  Bottom 1.016: D1.A R3.1 5.71,77.47 14.29,77.47 T1.S2
N$30
  Bottom 1.016: R28.1 R29.1 38.73,15.24 37.47,16.51 IC1.6
N$31
  Bottom 1.016: IC1.7 37.47,19.05 38.73,20.32 38.73,22.23 40.01,23.5 41.91,23.5 43.18,22.23 43.18,16.51 44.45,15.24 R29.2 | R29.2 TP2.TP | R31.1 48.26,17.78 R29.2
N$32
  Bottom 1.016: D3.A R24.1 33.02,73.34 T2.S2
N$33
  Bottom 1.016: L5.2 143.51,23.5
  Bottom 1.778: 143.51,23.5 143.51,29.21 146.05,31.75 CN3.3
N$34
  Bottom 1.016: R19.1 R18.1 19.68,28.57 28.57,28.57 | 28.57,28.57 29.21,28.57 | 29.21,28.57 43.81,28.57 R27.2 R28.2 | 29.21,28.57 C19.2 | 28.57,28.57 28.57,34.92 29.21,35.56 R25.2 31.75,35.56 | 31.75,35.56 31.75,50.8 C18.2 34.29,55.24 R24.2 R20.2 | 31.75,35.56 R21.1
N$35
  Bottom 0.406: R13.2 CN2.5
N$36
  Bottom 0.406: R30.1 Q3.3
N$37
  Bottom 0.406: R14.2 CN2.3
N$38
  Bottom 0.406: C20.1 IC2.4 74.3,21.59 76.2,23.5 76.2,29.21 78.74,31.75 95.89,31.75 97.16,30.48 97.16,27.94 95.89,26.67 R26.2
N$39  (via drill 0.7)
  Top 0.406: IC2.16 78.11,24.13 74.3,27.94 v73.66,27.94
  Bottom 0.406: v73.66,27.94 73.66,30.48 72.39,31.75 60.96,31.75 59.69,33.02 R34.1 | IC2.16 C30.2
N$41
  Bottom 1.016: IC3.1 C36.2 125.73,22.23 C35.+ 125.73,24.77 R36.1
N$42
  Top 1.016: IC1.8 33.02,21.59 31.75,20.32 C34.1
  Bottom 1.016: C32.+ R37.1 C34.1
N$43
  Bottom 0.406: IC2.15 C23.1 86.36,21.59 88.27,23.5 88.27,27.3 88.9,27.94 92.08,27.94 93.34,29.21 R30.2
N$44
  Bottom 0.406: R15.2 CN2.4
N$45
  Bottom 1.016: C9.2 C10.1 5.71,67.31 | 5.71,67.31 D1.K | R4.1 5.71,67.31
N$46
  Bottom 1.016: L3.2 143.51,36.83
  Bottom 1.778: 143.51,36.83 146.05,34.29 CN3.4
N$47
  Bottom 1.016: R4.2 C11.2 Q1.3
N$48
  Bottom 0.406: IC2.1 C17.2 66.04,29.21 63.5,26.67 58.42,26.67 R22.2 R17.1
N$49
  Bottom 1.016: Q2.2 R2.1 10.79,12.06 17.14,5.71 48.9,5.71 R5.1
N$50
  Bottom 2.794: CR1.NC 44.45,95.89 89.53,95.89 CR2.NC
N$51
  Bottom 0.406: L2.1 C39.2 98.42,38.1 97.79,37.47 Q3.2
N$52
  Bottom 0.406: R10.1 91.44,15.24 78.74,15.24 74.93,11.43 IC2.8 C3.1
N$53
  Bottom 2.794: CR3.NC 112.39,97.16 132.72,97.16 140.97,88.9 140.97,78.74 CR4.NC
N$54  (via drill 0.7)
  Top 0.406: v104.78,51.44 v106.68,53.34
  Bottom 0.406: CR3.COIL2 113.03,74.93 D5.A C27.1 106.68,63.5 v106.68,53.34 112.39,47.62 141.6,47.62 149.86,55.88 149.86,80.01 CR4.COIL2 | v104.78,51.44 93.98,40.64 76.83,40.64 76.2,40.01 C29.2 76.2,38.1 74.93,36.83 72.39,36.83 71.12,38.1 Q5.2
N$55
  Bottom 1.016: C21.1 T2.P2
  Bottom 2.032: T2.P2 36.2,76.2
  Bottom 2.794: 36.2,76.2 CR1.COM
N$56
  Bottom 2.794: CR2.COM CR3.COM
N$57
  Bottom 0.406: CR4.COIL1 151.13,73.66 151.13,55.24 142.24,46.35 126.36,46.35 125.73,45.72 | 125.73,45.72 125.09,46.35 111.76,46.35 105.41,52.7 105.41,67.31 C27.2 D5.K 107.95,74.93 CR3.COIL1 103.5,79.38 97.16,79.38 CR2.COIL1 95.25,74.93 D4.K C26.2 101.6,63.5 101.6,52.07 92.71,43.18 53.34,43.18 46.99,49.53 46.99,58.42 45.72,59.69 45.72,68.58 40.64,73.66 40.64,87.63 35.56,92.71 CR1.COIL1 | 125.73,45.72 L4.1
N$58
  Bottom 0.406: R35.2 Q5.3
N$59
  Bottom 0.406: R34.2 Q4.3
T1
  Bottom 1.016: D2.A R20.1 30.48,73.34 T2.S1

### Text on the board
Document: 100 | 4-3.3 | 5 | 5 | 160
_tPlace: Designed by JJ2PNX | http://www.momose.com/
_tNames: CN1(TRX) | R46 | R51 | R47 | R52 | R48 | R53 | R49 | R54 | R50 | R55 | R63 | R62 | R64 | CN5(ATU) | CR1 | CR4 | T1 | R3 | T2 | CR2 | CR3 | D4 | D5 | C26 | C27 | R66 | TC1 | C13 | C21 | TC2 | R20 | R24 | R57 | D1 | C9 | C10 | R58 | D2 | D3 | R56 | C14 | C22 | R61 | R65 | R67 | R38 | R43 | R39 | R44 | R40 | R45 | R41 | R59 | R42 | R60 | C18 | Full automatic ATU controller | L4 | Rev1.31 | Q4 | Q5 | R32 | C28 | C29 | C24 | R30 | L2 | C16 | R26 | Q3 | C11 | R25 | R21 | C30 | R6 | C15 | R8 | C25 | R34 | R35 | C23 | R7 | C39 | R4 | C5 | R10 | L1 | G | R33 | C17 | C6 | R13 | Q1 | IC2 | L3 | P | R9 | S | R18 | R27 | R22 | C31 | R23 | C35 | K | R1 | R17 | R36 | CN3(ATU) | IC1 | C19 | TXD | R19 | R28 | Q2 | S15 | R31 | C20 | S20 | L5 | R16 | R29 | R11 | C1 | GND | TUD | C36 | R2 | C37 | TP1 | TP2 | C2 | TUN | AUT | CN4(POW) | 12V | C34 | R5 | C3 | IC3 | D6 | AUD | C32 | C4 | GND | GND | C8 | R15 | C33 | CN2(CONT) | C7 | R14 | C38 | 94V-0 | R37 | C12 | R12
